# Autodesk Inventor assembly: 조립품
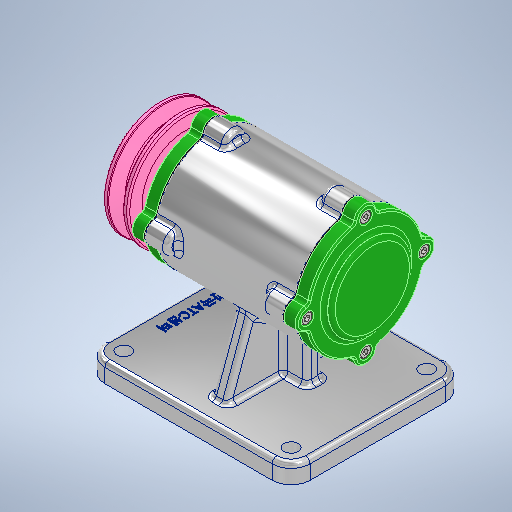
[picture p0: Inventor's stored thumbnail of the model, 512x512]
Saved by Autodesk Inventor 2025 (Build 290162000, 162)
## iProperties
Created: 2024-08
Part Number: 조립품
Document SubType Name: Assembly
Designer: 학생
Author: 학생
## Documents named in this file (12)
- C:\Users\학생\Desktop\740807V1003\조립품.iam
- C:\Users\학생\Desktop\740807V1003\본체.ipt
- C:\Users\학생\Desktop\740807V1003\Ű 4 x 4\Ű 4 x 4.ipt
- C:\Users\학생\Desktop\740807V1003\V-벨트풀리\V-벨트풀리.ipt
- C:\Users\학생\Desktop\740807V1003\개스킷\개스킷.ipt
- C:\Users\학생\Desktop\740807V1003\너트 M12 x 1.25\너트 M12 x 1.25.ipt
- C:\Users\학생\Desktop\740807V1003\뒤커버\뒤커버.ipt
- C:\Users\학생\Desktop\740807V1003\베어링 6204\베어링 6204.ipt
- C:\Users\학생\Desktop\740807V1003\볼트 M4 x 12\볼트 M4 x 12.ipt
- C:\Users\학생\Desktop\740807V1003\앞커버\앞커버.ipt
- C:\Users\학생\Desktop\740807V1003\오일실\오일실.ipt
- C:\Users\학생\Desktop\740807V1003\축\축.ipt
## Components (4 placed, 3 different names)
1. Ű 4 x 4:1 — 각도:1, 각도:2
2. V-벨트풀리:1 — 각도:2
3. 개스킷:1
4. 개스킷:2
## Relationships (2: Angle 2)
- 각도:1 [Angle]: Ű 4 x 4:1
- 각도:2 [Angle]: Ű 4 x 4:1 ↔ V-벨트풀리:1
